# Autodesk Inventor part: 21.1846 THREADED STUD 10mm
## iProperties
Created: 2007-03
Part Number: 21.1846 THREADED STUD 10mm
Document SubType Name: Modeling
Designer: Andy Moles
Material: Steel
Mass: 80.0158 g
Surface Area: 40.5758 cm^2
Volume: 10.1931 cm^3
Density: 7.85 g/cm^3
Author: Andy Moles
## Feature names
1. Revolution1
2. Extrusion1
3. Extrusion2
4. Extrusion3
5. Chamfer1
